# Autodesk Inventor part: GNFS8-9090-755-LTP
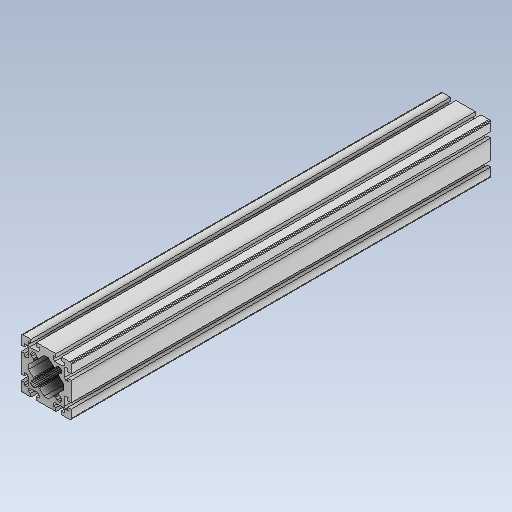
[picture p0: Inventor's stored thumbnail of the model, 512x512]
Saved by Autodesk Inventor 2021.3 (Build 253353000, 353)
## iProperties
Created: 2022-02
Part Number: GNFS8-9090-755-LTP
Material: 一般
Document SubType Name: Modeling
Designer: kengo
Density: 1 g/cm^3
Appearance: 既定
Author: kengo
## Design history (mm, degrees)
feature "GNFS8-9090-755-LTP"
node "ソリッド1"
